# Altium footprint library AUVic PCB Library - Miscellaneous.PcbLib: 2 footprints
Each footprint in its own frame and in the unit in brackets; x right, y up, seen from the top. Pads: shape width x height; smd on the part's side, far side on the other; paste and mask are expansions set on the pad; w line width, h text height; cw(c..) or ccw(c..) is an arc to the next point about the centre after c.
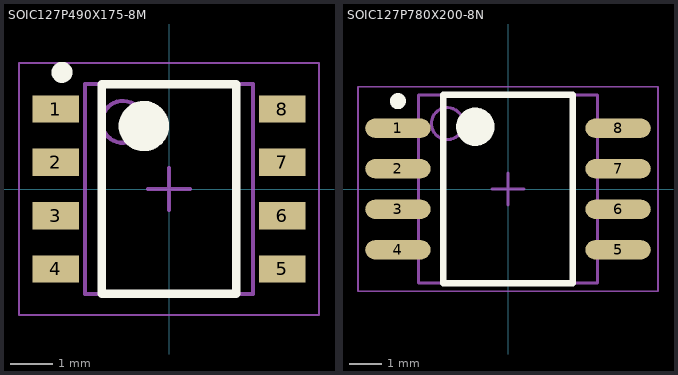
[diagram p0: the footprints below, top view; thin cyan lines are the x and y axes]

## SOIC127P490X175-8M [mm] "SOIC, 8-Leads, Body 4.90x3.90mm, Pitch 1.27mm, IPC Low Density"
height 1.75
pads (8):
  rect 1.1x0.65 smd: 1(-2.7,1.905) 2(-2.7,0.635) 3(-2.7,-0.635) 4(-2.7,-1.905) 5(2.7,-1.905) 6(2.7,-0.635) 7(2.7,0.635) 8(2.7,1.905)
Top Overlay:
  circle w0.25: c-2.55,2.78 r0.125
  circle w0.6: c-0.6,1.5 r0.3
  lines w0.2: -1.6,-2.5 -1.6,2.5 1.6,2.5 1.6,-2.5 -1.6,-2.5
Mechanical 13:
  circle w0.1: c-1.1,1.6 r0.5
  lines w0.1: -2,-2.5 -2,2.5 2,2.5 2,-2.5 -2,-2.5
Mechanical 15:
  lines w0.05: -3.575,-3 -3.575,3 3.575,3 3.575,-3 -3.575,-3
  lines w0.1: -0.5,0 0.5,0 ; 0,-0.5 0,0.5
3D body: height 1.75, standoff 0.1, extent -2,-2.5 2,2.5

## SOIC127P780X200-8N [mm] "SOIC, 8-Leads, Body 6.20x5.30mm, Pitch 1.27mm, IPC Medium Density"
height 2
pads (8):
  oval 2.05x0.6 smd: 1(-3.45,1.905) 2(-3.45,0.635) 3(-3.45,-0.635) 4(-3.45,-1.905) 5(3.45,-1.905) 6(3.45,-0.635) 7(3.45,0.635) 8(3.45,1.905)
Top Overlay:
  circle w0.6: c-1.025,1.95 r0.3
  circle w0.25: c-3.45,2.755 r0.125
  lines w0.2: -2.025,-2.95 2.025,-2.95 2.025,2.95 -2.025,2.95 -2.025,-2.95
Mechanical 13:
  circle w0.1: c-1.9,2.05 r0.5
  lines w0.1: -2.8,-2.95 2.8,-2.95 2.8,2.95 -2.8,2.95 -2.8,-2.95
Mechanical 15:
  lines w0.05: -4.7,-3.2 4.7,-3.2 4.7,3.2 -4.7,3.2 -4.7,-3.2
  lines w0.1: -0.5,0 0.5,0 ; 0,-0.5 0,0.5
3D body: height 2, standoff 0.1, extent -2.8,-2.95 2.8,2.95
3D body: height 1.63, standoff 0, extent -3,-2.475 3,2.425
